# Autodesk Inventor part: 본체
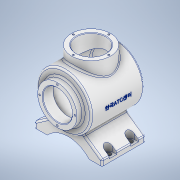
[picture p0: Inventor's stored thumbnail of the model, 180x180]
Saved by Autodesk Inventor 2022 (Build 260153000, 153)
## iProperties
Created: 2023-04
Part Number: 본체
Material: 알루미늄 6061
Document SubType Name: Modeling
Designer: Admin
Mass: 1296.69 g
Surface Area: 1060.45 cm^2
Volume: 480.256 cm^3
Density: 2.7 g/cm^3
Appearance: 알루미늄 - 평지
Author: Admin
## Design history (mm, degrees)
sketch "스케치1"
  geometry: L1 (0, -87.453)-(0, 84.575) reference; L2 (-10.134, 0)-(60.805, 0) reference; L3 (0, 60)-(36, 60); L4 (36, 60)-(36, 48); L5 (36, 48)-(50, 48); L6 (50, 48)-(50, -48.336); L7 (36, -60)-(0, -60); L8 (0, -60)-(0, 60); A1 r 113 centre (0, 53) between (0, -60) and (50, -48.336)
  constraints: 12 end point, 4 perpendicular, 4 point on line, 2 point on circle, 1 centre point, 1 collinear, 1 horizontal, 1 tangent, 1 other
  dimensions: "d4" = 120 distance between parallel lines of L7 L3; "d5" = 50 distance between parallel lines of L8 L6; "d6" = 36 distance between parallel lines of L8 L4; "d7" = 108 distance between parallel lines of L7 L5; "d8" = 226 diameter of A1
revolve "회전1" sketch "스케치1" stored, may be unused: angle "d9" = 90 deg
sketch "스케치2"
  geometry: L1 (-62, -77)-(62, -77); L2 (62, -77)-(62, -67); L3 (62, -67)-(17.576, -35.894); L4 (17.576, -35.894)-(-17.576, -35.894); L5 (-17.576, -35.894)-(-62, -67); L6 (-62, -67)-(-62, -77); L7 (0, -116.207)-(0, 77.701) reference; L8 (-111.694, 0)-(114.644, 0) reference; L9 (-25.806, -60)-(31.051, -60); A1 r 52.096 centre (0, -112.096) between (38.5, -77) and (-38.5, -77); 1 further point
  constraints: 14 end point, 2 horizontal, 2 parallel, 2 point on circle, 2 point on line, 1 centre point, 1 perpendicular, 1 symmetric about line, 1 tangent, 1 other
  dimensions: "d10" = 124 distance of L1.start L1.end; "d11" = 10 distance of L1.end L2.end; "d12" = 10 distance of L5.end L1.start; "d13" = 55 deg angle of L2 L3; "d14" = 55 deg angle of L6 L5; "d15" = 17 distance between parallel lines of L1 L9; "d16" = 77 distance between parallel lines of L8 L1; "d17" = 35.152 distance of L3.end L4.end; "d19" = 77 distance of A1.start A1.end
extrude "돌출1" join sketch "스케치2" stored distance "d20" = 80; taper "d21" = 0 deg
node "작업 평면1"
sketch "스케치4"
  geometry: L1 (-36, 60)-(36, 60) reference; C1 r 36 at (0, -2); 1 further point
  constraints: 1 centre point, 1 vertical alignment
  dimensions: "d29" = 72 diameter of C1; "d30" = 62 distance from line of L1 C1.centre
extrude "돌출2" join sketch "스케치4" distance "d31" = 30; taper "d32" = 0 deg
sketch "스케치3"
  geometry: L1 (-50, -48.336)-(50, -48.336) reference; L2 (-42.278, -40)-(-42.278, -40) reference; L3 (-42.278, -40)-(-42.278, 40) reference; L4 (-42.278, 40)-(-42.278, 40) reference; L5 (-42.278, 40)-(-42.278, -40) reference; L6 (-50, 48)-(50, 48) reference; L7 (-50, -48.336)-(50, -48.336) reference; L8 (-36, 60)-(36, 60) reference; L9 (-36, 48)-(36, 48) reference; L10 (-60, 40)-(-60, -40) reference; L11 (-77, -40)-(-77, 40) reference; L12 (-36, 60)-(36, 60) reference; L13 (0, 60)-(27, 60); L14 (27, 41)-(43, 41); L15 (43, 41)-(43, -43.887); L16 (27, 60)-(27, 41); L17 (0, 60)-(0, -53); A1 r 113 centre (0, 53) between (-50, -48.336) and (50, -48.336) reference; A2 r 106 centre (0, 53) between (0, -53) and (43, -43.887); 1 further point
  constraints: 10 end point, 2 perpendicular, 2 point on circle, 1 centre point, 1 horizontal, 1 midpoint, 1 parallel, 1 point on line
  dimensions: "d23" = 7 radial gap between concentric circles of A2 A1; "d24" = 27 distance of L13.start L13.end; "d25" = 43 distance between parallel lines of L17 L15; "d26" = 19 distance between parallel lines of L8 L14
revolve "회전2" sketch "스케치3" stored, may be unused: angle "d27" = 90 deg
sketch "스케치5"
  geometry: C1 r 36 at (0, 0) reference; C2 r 27 at (0, 0); 1 further point
  constraints: 1 centre point, 1 coincident
  dimensions: "d33" = 54 diameter of C2
extrude "돌출3" cut sketch "스케치5" distance "d34" = 40; taper "d35" = 0 deg
sketch "스케치6" dims "d36" = 65
  geometry: C1 r 27 at (0, 0) reference; C2 r 36 at (0, 0) reference; 3 further points
  constraints: 2 horizontal alignment, 1 coincident, 2 other
hole "구멍1" sketch "스케치6" at (-32.5, 0) diameter "d37" = 3.242; stored, may be unused: countersink angle "d41" = 90 deg, drill point angle "d43" = 118 deg; dims "d38" = 8, "d39" = 4, "d40" = 2, "d42" = 10
sketch "스케치7" dims "d47" = 65
  geometry: 3 further points
  constraints: 2 vertical alignment, 1 coincident, 2 other
hole "구멍2" sketch "스케치7" at (0, 32.5) diameter "d48" = 3.242; stored, may be unused: countersink angle "d52" = 90 deg, drill point angle "d54" = 118 deg; dims "d49" = 8, "d50" = 4, "d51" = 2, "d53" = 10
sketch "스케치8"
  geometry: L1 (23.5, -80)-(23.5, 0) reference; L2 (0, 0)-(23.5, 0) reference; L3 (0, -80)-(0, 0) reference; L4 (23.5, -80)-(0, -80) reference; L5 (-77, -80)-(-77, 0) reference; L6 (-100.5, 0)-(-77, 0) reference; L7 (-100.5, 0)-(-100.5, -80) reference; L8 (-77, -80)-(-100.5, -80) reference; C1 r 4.5 at (-92.5, -20); C2 r 4.5 at (-92.5, -60); C3 r 4.5 at (15.5, -60); C4 r 4.5 at (15.5, -20); 1 further point
  constraints: 4 centre point, 2 horizontal alignment, 2 vertical alignment
  dimensions: "d58" = 9 diameter of C4; "d59" = 9 diameter of C3; "d60" = 9 diameter of C2; "d61" = 9 diameter of C1; "d62" = 40 distance of C4.centre C3.centre; "d63" = 20 distance from line of L2 C4.centre; "d64" = 108 distance of C1.centre C4.centre; "d65" = 8 distance from line of L1 C4.centre
extrude "돌출4" cut sketch "스케치8" distance "d66" = 6; taper "d67" = 0 deg
sketch "스케치9"
  geometry: L1 (0, 7)-(-8, 7); L2 (-8, -60)-(-8, 20) reference; L3 (-8, 7)-(-8, -7); L4 (-8, -7)-(0, -7); L5 (0, -33)-(-8, -33); L6 (0, -47)-(-8, -47); L7 (-8, -47)-(-8, -33); L8 (108, 7)-(116, 7); L9 (116, -60)-(116, 20) reference; L10 (108, -7)-(116, -7); L11 (108, -33)-(116, -33); L12 (108, -47)-(116, -47); L13 (116, 7)-(116, -7); L14 (116, -33)-(116, -47); C1 r 4.5 at (0, 0) reference; C2 r 4.5 at (0, -40) reference; C3 r 4.5 at (108, -40) reference; C4 r 4.5 at (108, 0) reference; A1 r 7 centre (0, 0) between (0, 7) and (0, -7); A2 r 7 centre (0, -40) between (0, -33) and (0, -47); A3 r 7 centre (108, -40) between (108, -33) and (108, -47); A4 r 7 centre (108, 0) between (108, 7) and (108, -7); 1 further point
  constraints: 24 end point, 8 point on circle, 8 tangent, 7 point on line, 4 centre point, 4 coincident, 4 equal length, 4 perpendicular, 2 horizontal, 1 vertical
  dimensions: "d68" = 14 diameter of A4; "d69" = 14 diameter of A3 (= d68); "d70" = 14 diameter of A2; "d71" = 14 diameter of A1 (= d70); "d72" = 8 distance of L3.end L4.end
extrude "돌출5" cut sketch "스케치9" distance "d73" = 20; taper "d74" = 0 deg
sketch "스케치10"
  geometry: L1 (-27, 60)-(27, 60) reference; 2 further points
  constraints: 1 vertical alignment, 1 other
  dimensions: "d75" = 62 distance from line of L1 point (0, -2)
feature "엠보싱1" sketch "스케치10" dims "d76" = 0.5, "d77" = 0
fillet "모깎기1" dims "d78" = 3
fillet "모깎기2" dims "d79" = 3
chamfer "모따기1" distance "d80" = 1; stored, may be unused: second distance "d81" = 2, angle "d82" = 45 deg
fillet "모깎기3" dims "d83" = 3
fillet "모깎기4" dims "d84" = 3
node "솔리드1"
pattern_circular "원형 패턴1" dims angle "d45" = 360 deg
pattern_circular "원형 패턴2" dims angle "d56" = 360 deg
node "투영된 루프1"
node "투영된 루프2"
node "투영된 루프3"
node "투영된 루프4"
node "투영된 루프5"
node "투영된 루프6"
node "투영된 루프7"
node "투영된 루프8"
node "투영된 루프9"
node "투영된 루프10"
node "투영된 루프11"
feature "A9D066F2-1C7D-4E18-AEED-F7BC21143FA4" dims "d37" = 3.242, "d38" = 8, "d39" = 4, "d40" = 2, "d41" = 90 deg, "d42" = 10, "d43" = 118 deg
other parameters: "d22" = 7, "d28" = 65
